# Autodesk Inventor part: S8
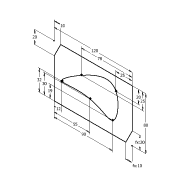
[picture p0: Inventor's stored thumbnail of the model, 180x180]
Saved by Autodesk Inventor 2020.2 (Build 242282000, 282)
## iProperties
Created: 2013-12
Part Number: S8
Material: Ogólny
Document SubType Name: Modeling
Designer: F.Stasiak
Density: 1 g/cm^3
Appearance: Domyślna
Manager: www.cadconsulting.pl
Company: Fabian Stasiak CAD Consulting
Author: F.Stasiak
Subject: Zbiór ćwiczeń. Autodesk Inventor 2020. Kurs podstawowy
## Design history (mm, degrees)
sketch "Szkic1"
  geometry: L1 (0, 0)-(110, 0); L2 (120, 20)-(120, 80); L3 (120, 80)-(10, 80); L4 (0, 60)-(0, 0); L5 (0, 60)-(10, 80); L6 (120, 20)-(110, 0); 7 further points
  constraints: 12 end point, 4 point on line, 2 parallel, 1 horizontal, 1 perpendicular, 5 other
  dimensions: "d0" = 120 distance of point (0, 80) L2.end; "d1" = 80 distance of L2.end point (120, 0); "d2" = 32 distance from line of point (12, 32) L1; "d3" = 12 distance from line of point (12, 32) L4; "d4" = 55 distance from line of point (55, 30) L4; "d5" = 90 distance from line of point (90, 19) L4; "d6" = 30 distance from line of L1 point (55, 30); "d7" = 19 distance from line of L1 point (90, 19); "d8" = 20 distance from line of L3 point (95, 60); "d9" = 25 distance from line of L3 point (42, 55); "d10" = 25 distance from line of point (95, 60) L2; "d11" = 78 distance from line of point (42, 55) L2; "d12" = 20 distance of L4.start point (0, 80); "d13" = 10 distance of L3.end point (0, 80); "d14" = 20 distance of L2.start point (120, 0) (= d12); "d15" = 10 distance of L1.end point (120, 0) (= d13)
